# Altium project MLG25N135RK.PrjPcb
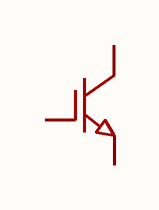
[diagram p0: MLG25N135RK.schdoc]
1 sheet, 1 parts. Net scope: global (net labels, ports and power ports of the same name join across sheets).

## Sheet MLG25N135RK.schdoc
size 127 x 101 mm

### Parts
Q?  mlg25n135rk  [TO-247-3_L15.8-W5.0-P5.44-L]  (value not drawn)

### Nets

Not connected (* = marked no-connect by the designer): Q? 1(G) 2(C) 3(E)

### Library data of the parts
Q? = mlg25n135rk: IGBT类型:NPT(非穿通型);耗散功率(Pd):208W;集射极击穿电压(Vces):1.35kV;集电极电流(Ic):25A;; Manufacturer: minos(迈诺斯); AddInBom: yes; ModelId: 2dc33f6e48bd44aa838c2b9e2b85eb16; ModelTransform: 622.04631,185.078,0,0,0,0,-0.003,13.778,-196.85; Pd - Power Dissipation: 208W; Collector-Emitter Breakdown Voltage (Vces): 1.35kV; Current - Collector(Ic): 25A; Current - Collector Pulsed (Icm): 75A; Collector Cut-Off Current (Ices): 1uA; Vce Saturation(VCE(sat)): 2.5V@25A,15V; Gate-Emitter Threshold Voltage (Vge(th)@Ic): 5.5V@1mA; Gate Charge(Qg): 142nC@25A,15V; Input Capacitance(Cies): 2.37nF@30V; Output Capacitance(Coes): 59pF; Reverse Transfer Capacitance (Cres): 43pF; Td(on): 34ns; Td(off): 198ns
